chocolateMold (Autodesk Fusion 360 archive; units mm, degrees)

design "chocolateMold" references "bantam tools desktop cnc milling machine"
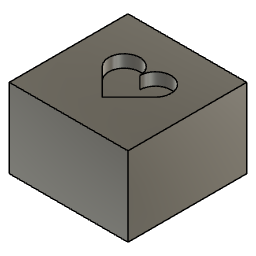
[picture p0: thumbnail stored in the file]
box_primitive "BoxPrimitive1" DistanceX 38.1 DistanceY 38.1 DistanceZ 25.4 OffsetDistanceX 0 OffsetDistanceY 0
sketch "Sketch2" plane through (0, 0, 25.4) normal (0, 0, 1) x axis (-1, 0, 0)
  line L1 (0, -38.1) -> (-38.1, -38.1)
  line L2 (0, 0) -> (0, -38.1)
  line L3 (-38.1, 0) -> (0, 0)
  line L4 (-38.1, -38.1) -> (-38.1, 0)
  line L5 (-38.1, -38.1) -> (0, -38.1)
  line L6 (-19.05, -22.86) -> (-19.05, -38.1)
  line L7 (-14.05, -22.86) -> (-19.05, -22.86)
  line L8 (-24.05, -22.86) -> (-19.05, -22.86)
  line L9 (-19.05, -22.86) -> (-14.05, -22.86)
  line L10 (-10.5145, -19.3245) -> (-14.05, -22.86)
  line L11 (-19.05, 0) -> (-19.05, -38.1)
  line L12 (-37.1633, 7.3244) -> (-10.5145, -19.3245)
  line L13 (-0.9367, 7.3244) -> (-27.5855, -19.3245)
  arc A1 centre (-14.05, -22.86) radius 5 clockwise from (-10.5145, -19.3245) to (-19.05, -22.86)
  arc A2 centre (-24.05, -22.86) radius 5 clockwise from (-19.05, -22.86) to (-27.5855, -19.3245)
  point P3 (0, -38.1)
  point P6 (0, -38.1)
  point P2 (-38.1, -38.1)
  point P7 (-38.1, -38.1)
  point P8 (-19.05, -38.1)
  point P10 (-14.05, -22.86)
  point P12 (-14.05, -22.86)
  point P14 (-19.05, 0)
  point P9 (-19.05, -22.86)
  point P17 (-19.05, -22.86)
  point P13 (-10.5145, -19.3245)
  point P18 (-27.5855, -19.3245)
  point P15 (-37.1633, 7.3244)
  point P19 (-0.9367, 7.3244)
  point P11 (-24.05, -22.86)
  coincident P3 P6
  coincident P2 P7
  midpoint L1 P8
  perpendicular L3 L6
  perpendicular L6 L7
  perpendicular L6 L8
  coincident P10 P12
  midpoint L3 P14
  symmetric P9 L11 P17
  symmetric P13 L11 P18
  symmetric A1 L11 A2
  symmetric L11 P15 P19
  dimension "d15" distance P8 P9 = 15.24
  dimension "d16" distance P9 P10 = 5
  dimension "d17" distance P9 P11 = 5
  dimension "d18" angle L9 L10 = 135
  dimension "d19" angle L11 L12 = 135
extrude "Extrude2" cut sketch "Sketch2" profile of A1 L12 A2 L13 against normal blind 4
scale "Scale4"

design "bantam tools desktop cnc milling machine"
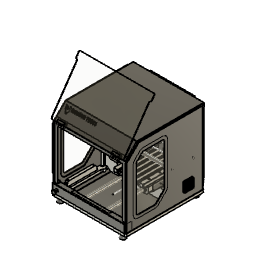
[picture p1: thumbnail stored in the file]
parameter "d2141_1" = 0
parameter "d2142_1" = 0
parameter "d2143_1" = 0
parameter "d2144_1" = 0
parameter "d2153_1" = 0
parameter "d2154_1" = 0
parameter "d2155_1" = 0
parameter "d2156_1" = 0
parameter "d813_1" = 0
parameter "d814_1" = 0
parameter "d815_1" = 0
parameter "d816_1" = 0
parameter "d825_1" = 0
parameter "d826_1" = 0
parameter "d827_1" = 0
parameter "d828_1" = 0
parameter "d573_1" = 0
parameter "d574_1" = 0
parameter "d575_1" = 0
parameter "d576_1" = 0
parameter "d581_1" = 0
parameter "d582_1" = 0
parameter "d583_1" = 0
parameter "d584_1" = 0
parameter "d2050_1" = 0
parameter "d2051_1" = 0
parameter "d2052_1" = 0
parameter "d2053_1" = 0
parameter "d2675_1" = 0
parameter "d2676_1" = 0
parameter "d2677_1" = 0
parameter "d2678_1" = 0
parameter "d2693_1" = 0
parameter "d2694_1" = 0
parameter "d2695_1" = 0
parameter "d2696_1" = 0
parameter "d5_1" = 2.54
parameter "d2829_1" = 0
parameter "d2830_1" = 0
parameter "d2831_1" = 0
parameter "d2832_1" = 0
parameter "Slot_Spacing" = 30
parameter "Slot_Spacing_1" = 30
parameter "d36_1" = 2.5
parameter "d636_1" = 1.062
parameter "d1796_1" = 1.905
parameter "d1824_1" = 1.2192
parameter "d2014_1" = 0.762
parameter "d4_1" = 1.2192
parameter "d5_1_1" = 0.762
parameter "d36_4" = 2.5
parameter "d636_2" = 1.062
parameter "d1796_2" = 1.905
parameter "d1824_2" = 1.2192
parameter "d1988_1" = 1.524
parameter "d2014_2" = 0.762
parameter "d36_5" = 2.5
parameter "d636_3" = 1.062
parameter "d1796_3" = 1.905
parameter "d1824_3" = 1.2192
parameter "d2014_3" = 0.762
parameter "d2062" = 0
parameter "d2063" = 0
parameter "d2064" = 0
parameter "d2065" = 0
parameter "d2244" = 0
parameter "d2245" = 0
parameter "d2246" = 0
parameter "d2247" = 0
parameter "d2141" = 0
parameter "d2142" = 0
parameter "d2143" = 0
parameter "d2144" = 0
parameter "d2153" = 0
parameter "d2154" = 0
parameter "d2155" = 0
parameter "d2156" = 0
parameter "d813" = 0
parameter "d814" = 0
parameter "d815" = 0
parameter "d816" = 0
parameter "d825" = 0
parameter "d826" = 0
parameter "d827" = 0
parameter "d828" = 0
parameter "d573" = 0
parameter "d574" = 0
parameter "d575" = 0
parameter "d576" = 0
parameter "d581" = 0
parameter "d582" = 0
parameter "d583" = 0
parameter "d584" = 0
parameter "d2050" = 0
parameter "d2051" = 0
parameter "d2052" = 0
parameter "d2053" = 0
parameter "d2675" = 0
parameter "d2676" = 0
parameter "d2677" = 0
parameter "d2678" = 0
parameter "d2693" = 0
parameter "d2694" = 0
parameter "d2695" = 0
parameter "d2696" = 0
parameter "d270_1" = 38.1
parameter "d270_2" = 38.1
parameter "d2829" = 0
parameter "d2830" = 0
parameter "d2831" = 0
parameter "d2832" = 0
parameter "d270" = 38.1
parameter "d1572" = 2.54
parameter "d1573" = 1.5875
parameter "d1588" = 2.54
parameter "d447" = 0
parameter "d448" = 0
parameter "d449" = 0
parameter "d450" = 0
parameter "d459" = 0
parameter "d460" = 0
parameter "d461" = 0
parameter "d462" = 0
parameter "d2015" = 0
parameter "d2016" = 0
parameter "d2017" = 0
parameter "d2018" = 0
parameter "d2046" = 0
parameter "d2047" = 0
parameter "d2048" = 0
parameter "d2049" = 0
parameter "d688" = 0
parameter "d689" = 0
parameter "d690" = 0
parameter "d691" = 0
parameter "d1260" = 0
parameter "d1261" = 0
parameter "d1262" = 0
parameter "d1263" = 0
parameter "d1272" = 0
parameter "d1273" = 0
parameter "d1274" = 0
parameter "d1275" = 0
parameter "d486" = 0
parameter "d487" = 0
parameter "d488" = 0
parameter "d489" = 0
parameter "d719" = 0
parameter "d720" = 0
parameter "d721" = 0
parameter "d722" = 0
parameter "d1284" = 0
parameter "d1285" = 0
parameter "d1286" = 0
parameter "d1287" = 0
parameter "d1296" = 0
parameter "d1297" = 0
parameter "d1298" = 0
parameter "d1299" = 0
parameter "d1308" = 0
parameter "d1309" = 0
parameter "d1310" = 0
parameter "d1311" = 0
parameter "d684" = 0
parameter "d685" = 0
parameter "d686" = 0
parameter "d687" = 0
parameter "d696" = 0
parameter "d697" = 0
parameter "d698" = 0
parameter "d699" = 0
parameter "d715" = 0
parameter "d716" = 0
parameter "d717" = 0
parameter "d718" = 0
parameter "d731" = 0
parameter "d732" = 0
parameter "d733" = 0
parameter "d734" = 0
parameter "d337" = 0
parameter "d338" = 0
parameter "d339" = 0
parameter "d340" = 0
parameter "d700" = 0
parameter "d701" = 0
parameter "d702" = 0
parameter "d703" = 0
parameter "d727" = 0
parameter "d728" = 0
parameter "d729" = 0
parameter "d730" = 0
parameter "d36" = 2.5
parameter "d636" = 1.062
parameter "d1796" = 1.905
parameter "d1824" = 1.2192
parameter "d2014" = 0.762
parameter "d3" = 2.5
parameter "d151_1" = 55.016
named bodies: "Body1 (1)", "Body1 (2)", "Body1 (3)", "Body1 (4)", "Body2"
